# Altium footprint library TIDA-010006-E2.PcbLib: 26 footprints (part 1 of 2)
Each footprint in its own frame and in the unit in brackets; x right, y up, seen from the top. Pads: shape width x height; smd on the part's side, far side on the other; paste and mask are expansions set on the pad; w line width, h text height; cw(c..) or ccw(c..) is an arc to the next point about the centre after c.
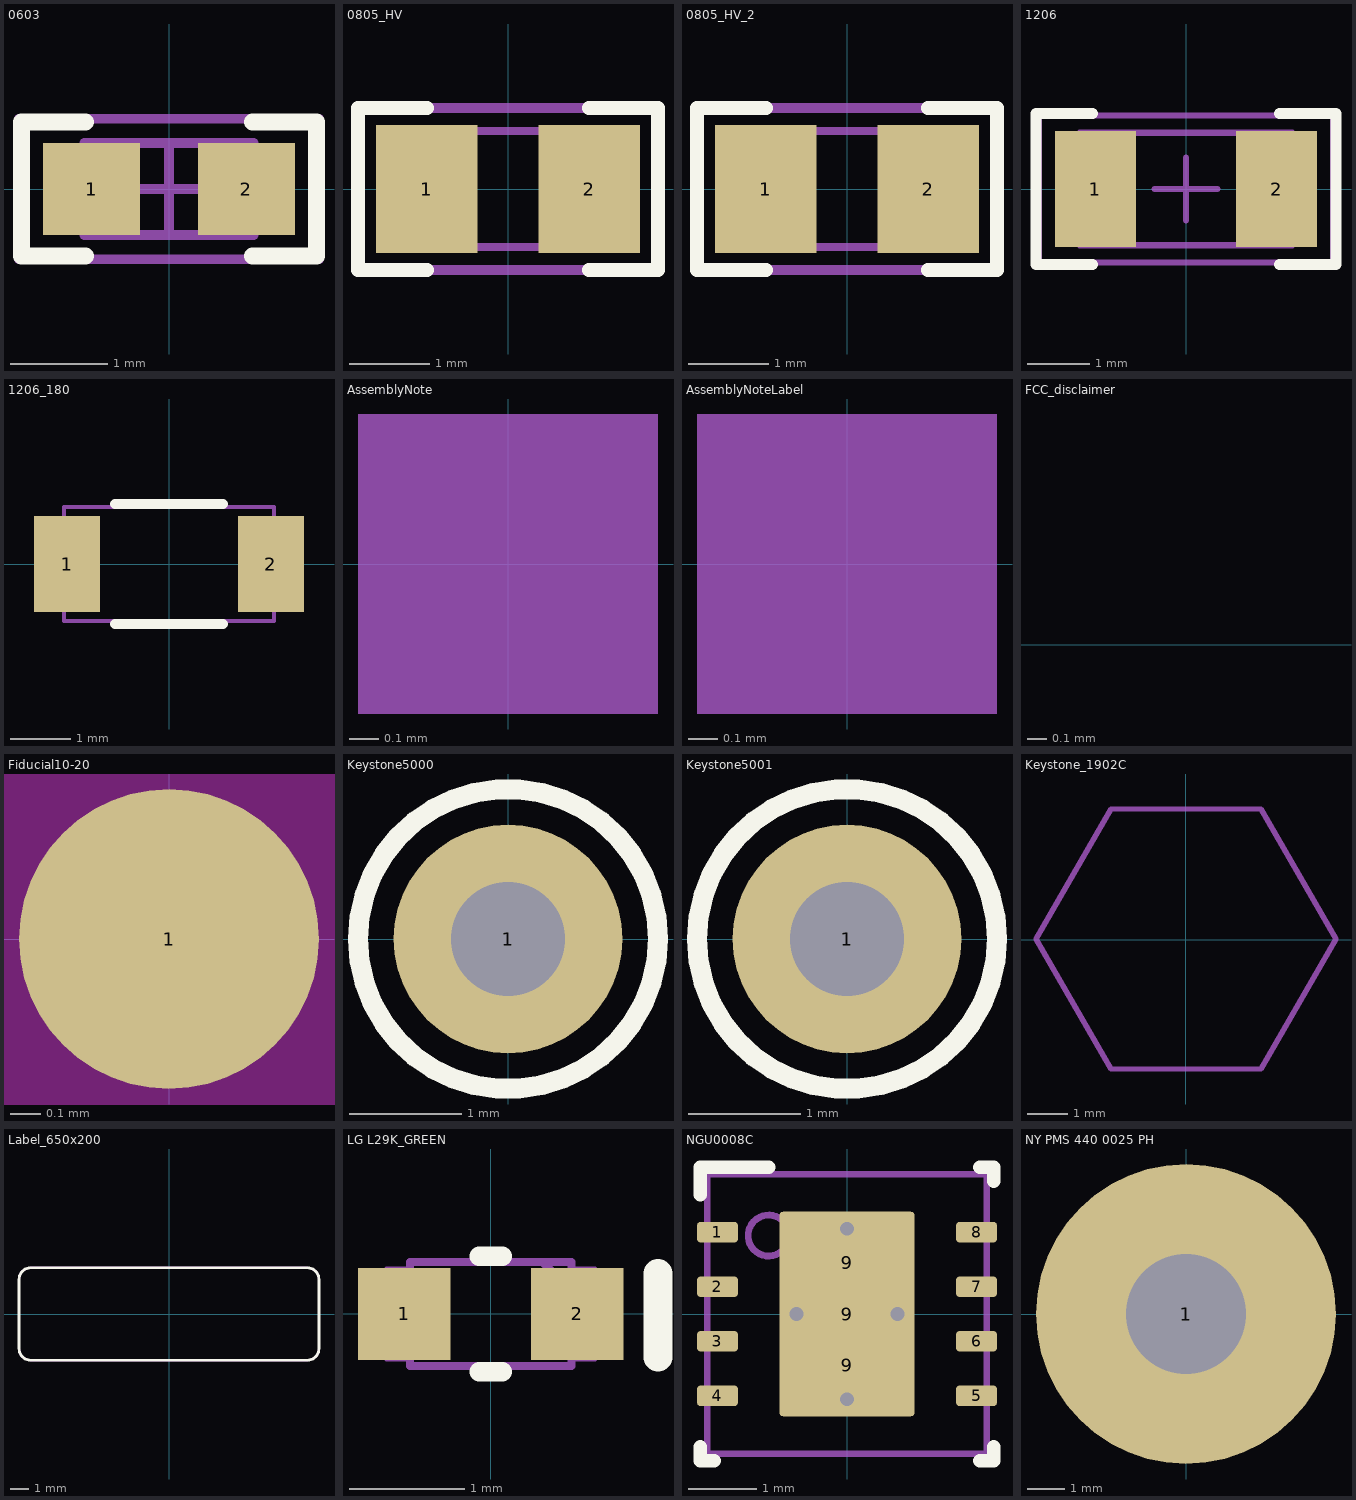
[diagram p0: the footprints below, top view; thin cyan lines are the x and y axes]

## 0603 [mm] "0603 from SM-752 data"
height 1
pads (2):
  rect 1x0.95 smd: 1(-0.8,0) 2(0.8,0)
Top Overlay:
  lines w0.178: -0.864,-0.691 -1.524,-0.691 -1.524,0.693 -0.864,0.693 ; 0.864,-0.691 1.524,-0.691 1.524,0.693 0.864,0.693
Mechanical 5:
  lines w0.1: -1.55,-0.725 -1.55,0.725 1.55,0.725 1.55,-0.725 -1.55,-0.725
  text ".Designator" at -0.956,-0.381 h0.76
Mechanical 13:
  lines w0.1: -0.55,-0.475 -0.55,0.475 ; 0.55,-0.475 0.55,0.475 ; -0.875,-0.475 0.875,-0.475 0.875,0.475 -0.875,0.475 -0.875,-0.475
Mechanical 15:
  lines w0.1: -0.475,0 0.475,0 ; 0,-0.475 0,0.475 ; -1.55,-0.725 1.55,-0.725 1.55,0.725 -1.55,0.725 -1.55,-0.725
3D body: height 1, standoff 0, extent -0.874,-0.474 -0.551,0.474
3D body: height 1, standoff 0, extent -0.549,-0.474 0.549,0.474
3D body: height 1, standoff 0, extent 0.551,-0.474 0.874,0.474

## 0805_HV [mil] "0805 with 30mil clearance between pads"
height 57.09
pads (2):
  rect 50x63 smd: 1(-40,0) 2(40,0)
Top Overlay:
  lines w7: -40,-40 -74,-40 -74,0 -74,40 -40,40 ; 40,-40 74,-40 74,0 74,40 40,40
Mechanical 5:
  lines w5: -74,-40 -74,40 74,40 74,-40 -74,-40
  text ".Designator" at 21.26,21.57 h30
Mechanical 13:
  lines w3.94: -25.59,-28.54 -25.59,28.54 ; 25.59,-28.54 25.59,28.54 ; -43.31,-28.54 -43.31,28.54 43.31,28.54 43.31,-28.54 -43.31,-28.54
3D body: height 57.09, standoff 0, extent 25.61,-28.52 43.29,28.52
3D body: height 57.09, standoff 0, extent -25.57,-28.52 25.57,28.52
3D body: height 57.09, standoff 0, extent -43.29,-28.52 -25.61,28.52

## 0805_HV_2 [mil]
pads (2):
  rect 50x63 smd: 1(-40,0) 2(40,0)
Top Overlay:
  lines w7: -40,-40 -74,-40 -74,0 -74,40 -40,40 ; 40,-40 74,-40 74,0 74,40 40,40
Mechanical 5:
  lines w5: -74,-40 74,-40 74,40 -74,40 -74,-40
  text ".Designator" at -53.22,-15.46 h30
Mechanical 13:
  lines w3.94: -25.59,-28.54 -25.59,28.54 ; 25.59,-28.54 25.59,28.54 ; -43.31,-28.54 43.31,-28.54 43.31,28.54 -43.31,28.54 -43.31,-28.54
3D body: height 57.09, standoff 0, extent -43.29,-28.52 -25.61,28.52
3D body: height 57.09, standoff 0, extent -25.57,-28.52 25.57,28.52
3D body: height 57.09, standoff 0, extent 25.61,-28.52 43.29,28.52

## 1206 [mm] "1206 from SM-752 data"
height 1.35
pads (2):
  rect 1.3x1.85 smd: 1(-1.45,0) 2(1.45,0)
Top Overlay:
  lines w0.178: -1.5,-1.21 -2.4,-1.21 -2.4,1.21 -1.5,1.21 ; 1.5,-1.21 2.4,-1.21 2.4,1.21 1.5,1.21
Mechanical 5:
  lines w0.1: -1.7,-0.9 1.7,-0.9 1.7,0.9 -1.7,0.9 -1.7,-0.9
  text ".Designator" at 0.419,0.286 h0.76
Mechanical 13:
  lines w0.1: -1.2,-0.9 -1.2,0.9 ; 1.2,-0.9 1.2,0.9 ; -1.7,-0.9 1.7,-0.9 1.7,0.9 -1.7,0.9 -1.7,-0.9
Mechanical 15:
  lines w0.1: -0.5,0 0.5,0 ; 0,-0.5 0,0.5 ; -2.35,-1.175 2.35,-1.175 2.35,1.175 -2.35,1.175 -2.35,-1.175
3D body: height 1.35, standoff 0, extent -1.699,-0.899 -1.201,0.899
3D body: height 1.35, standoff 0, extent -1.199,-0.899 1.199,0.899
3D body: height 1.35, standoff 0, extent 1.201,-0.899 1.699,0.899

## 1206_180 [mm] "1206_180"
height 1.8
pads (2):
  rect 1.1x1.6 smd: 1(-1.7,0) 2(1.7,0)
Top Overlay:
  lines w0.17: -0.9,-1 0.9,-1 ; -0.9,1 0.9,1
Mechanical 5:
  lines w0.07: -1.75,-0.95 1.75,-0.95 1.75,0.95 -1.75,0.95 -1.75,-0.95
  text ".Designator" at 0.896,0.345 h0.76
3D body: height 1.8, standoff 0, extent -1.749,-0.949 -1.301,0.949
3D body: height 1.8, standoff 0, extent -1.299,-0.949 1.299,0.949
3D body: height 1.8, standoff 0, extent 1.301,-0.949 1.749,0.949

## AssemblyNote [mm] "Assembly Note"
Mechanical 5:
  rectangle: -0.508,-0.508 0.508,0.508
  text ".Comment" at 1.143,-0.508 h1.02
  text ".Designator" at -4.191,-0.508 h1.02

## AssemblyNoteLabel [mm] "Assembly Note for PCB Labels"
Mechanical 5:
  rectangle: -0.508,-0.508 0.508,0.508
  text ".Designator" at -4.191,-0.508 h1.02
  text "Install label in silkscreened box after final wash.  Text shall be 8 pt font.  Text shall be per the Label Table in the PDF schematic." at 1.143,-0.508 h1.02

## FCC_disclaimer [mm]
height 2.62
Top Overlay:
  text "For evaluation only; not FCC approved for resale." at -15.928,-0.353 h1.52

## Fiducial10-20 [mm]
pads (1):
  round 1 smd mask+0.5: 1(0,0)
Top Layer keep-out:
  circle w1.178: c0,0 r0.5

## Keystone5000 [mil] "For Keystone 500x miniature loop terminals"
height 181.1
pads (1):
  round 80 hole 40: 1(0,0)
Top Overlay:
  circle w7: c0,0 r52.5
Mechanical 5:
  circle w3.94: c0,0 r52.5
  text ".Designator" at -25.83,158.43 h30
3D body "Keystone_5000.stp": height 181.97, standoff -118.11, extent -49,-49 49.04,49.24

## Keystone5001 [mil] "For Keystone 500x miniature loop terminals"
height 181.1
pads (1):
  round 80 hole 40: 1(0,0)
Top Overlay:
  circle w7: c0,0 r52.5
Mechanical 5:
  circle w3.94: c0,0 r52.5
  text ".Designator" at -28.42,156.4 h30
3D body "Keystone_5001.stp": height 181.97, standoff -118.11, extent -49,-49 49.04,49.24

## Keystone_1902C [mil] "Hex Standoff, 4-40 threaded, nylon"
height 500
pads (1):
  round 1 on Mech3: 0(0,0)
Mechanical 5:
  lines w5: -145.29,0.49 -72.56,126.47 72.92,126.47 145.65,0.49 72.92,-125.49 -72.56,-125.49 -145.29,0.49
  text ".Designator" at -60,-20 h40
3D body "Keystone_1902C.stp": height 501, standoff 1, extent -144.95,-125.98 146,125.98

## Label_650x200 [mil] "Thermal Transfer Label"
height 1
pads (1):
  round 1 on Mech13: 0(0,0)
Top Overlay:
  lines w6: -325,-75 ccw(c-300,-75) -300,-100 300,-100 ccw(c300,-75) 325,-75 325,75 ccw(c300,75) 300,100 -300,100 ccw(c-300,75) -325,75 -325,-75
Mechanical 5:
  lines w5: -325,-75 ccw(c-300,-75) -300,-100 300,-100 ccw(c300,-75) 325,-75 325,75 ccw(c300,75) 300,100 -300,100 ccw(c-300,75) -325,75 -325,-75
  text ".Designator" at -60,-20 h30
3D body: height 1, standoff 0, extent -325.02,-100.02 325.02,100.02

## LG L29K_GREEN [mm] "OSRAM"
height 0.67
pads (2):
  rect 0.8x0.8 smd paste-0.4: 1(-0.75,0) 2(0.75,0)
Top Overlay:
  lines w0.17: -0.1,-0.5 0.1,-0.5 ; -0.1,0.5 0.1,0.5
  lines w0.25: 1.45,-0.375 1.45,0.35
Top Paste:
  rectangle: -1.1,-0.35 -0.5,0.35
  rectangle: 0.5,-0.35 1.1,0.35
Mechanical 5:
  lines w0.07: 0.7,0.375 0.9,0.375 0.9,-0.375 0.7,-0.375 ; 0.7,-0.375 0.7,0.2 ; 0.7,-0.375 0.7,-0.45 -0.7,-0.45 -0.7,-0.375 -0.9,-0.375 -0.9,0.375 -0.7,0.375 -0.7,0.45 0.7,0.45 ; 0.7,0.2 0.45,0.45 0.7,0.45 ; 0.7,0.2 0.7,0.45
  text ".Designator" at 1.411,-0.375 h0.76
3D body: height 0.18, standoff 0, extent -0.899,-0.374 -0.701,0.374
3D body: height 0.18, standoff 0, extent 0.701,-0.374 0.899,0.374
3D body: height 0.18, standoff 0, extent -0.699,-0.449 0.699,0.449
3D body: height 0.67, standoff 0.18, extent -0.699,-0.449 0.699,0.449
3D body: height 0.67, standoff 0.65, extent 0.451,0.201 0.699,0.449

## NGU0008C [mm] "SON, 8-Leads, Body 4x4mm, Pitch 0.8mm"
height 0.8
pads (11):
  rrect33% 0.6x0.3 smd: 1(-1.9,1.2) 2(-1.9,0.4) 3(-1.9,-0.4) 4(-1.9,-1.2) 5(1.9,-1.2) 6(1.9,-0.4) 7(1.9,0.4) 8(1.9,1.2)
  rrect50% 1.75x1.31 on Top Paste: 9(0,-0.755) 9(0,0.755)
  rrect5% 1.98x3 smd paste-1.5: 9(0,0)
via -0.74,0 diameter 0.5 hole 0.2
via 0.74,0 diameter 0.5 hole 0.2
via 0,1.25 diameter 0.5 hole 0.2
via 0,-1.25 diameter 0.5 hole 0.2
Top Overlay:
  lines w0.2: -2.15,-1.95 -2.15,-2.15 -1.95,-2.15 ; -2.15,1.75 -2.15,2.15 -1.15,2.15 ; 1.95,-2.15 2.15,-2.15 2.15,-1.95 ; 1.95,2.15 2.15,2.15 2.15,1.95
Mechanical 5:
  circle w0.1: c-1.15,1.15 r0.3
  lines w0.1: -2.05,-2.05 2.05,-2.05 2.05,2.05 -2.05,2.05 -2.05,-2.05
  text ".Designator" at 0.635,0.152 h0.76
3D body "NGU0008C.stp": height 0.77, standoff 0, extent -2,-2 2,2

## NY PMS 440 0025 PH [mm] "4-40 nylon screw and mounting hole"
height 1.905
pads (1):
  round 8 hole 3.2: 1(0,0)
Mechanical 5:
  circle w0.127: c0,0 r3.789
  text ".Designator" at -1.524,-0.508 h0.76
3D body "B_F_NY PMS 440 0025 PH.stp": height 2.69, standoff -8.74, extent -3.302,-3.3 3.296,3.3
